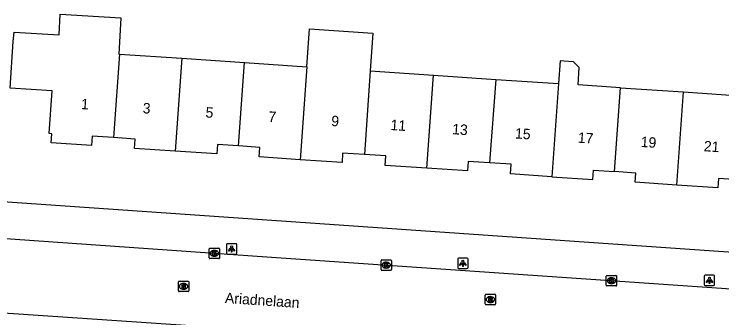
# Model space of a CAD drawing. Extents: x 161848 to 162726, y 385382 to 386521.
# Drawn here: x 162018.3 to 162086.1, y 385519.3 to 385548.4 of the extents above; entities that cross this region are included whole.
import ezdxf

# ---------------------------------------------------------------- set-up
doc = ezdxf.new("R2010")
doc.units = 0
for name, color, linetype in [('IMGEO_Kolk', 7, 'Continuous'), ('IMGEO_Lichtpunt', 7, 'Continuous'), ('IMGEO_Openbare_ruimte_label', 7, 'Continuous'), ('IMGEO_Pand', 7, 'Continuous'), ('IMGEO_Pand_nummerreeks', 7, 'Continuous'), ('IMGEO_Rijbaan_lokaal_open', 7, 'Continuous'), ('IMGEO_Rioolput', 7, 'Continuous'), ('IMGEO_Voetpad_open', 7, 'Continuous')]:
    doc.layers.add(name, color=color, linetype=linetype)

msp = doc.modelspace()

# ---------------------------------------------------------------- linework, layer by layer
at = {"layer": 'IMGEO_Kolk'}
for p, q in [((162037.014, 385525.047), (162037.014, 385525.899)), ((162037.089, 385525.973), (162037.941, 385525.973)), ((162037.502, 385525.753), (162037.527, 385525.753)), ((162038.015, 385525.899), (162038.015, 385525.047)), ((162037.941, 385524.973), (162037.089, 385524.973)), ((162037.525, 385525.193), (162037.5, 385525.193)), ((162053.474, 385523.918), (162053.474, 385524.77)), ((162053.549, 385524.844), (162054.401, 385524.844)), ((162054.475, 385524.77), (162054.475, 385523.918)), ((162053.985, 385524.064), (162053.96, 385524.064)), ((162053.962, 385524.624), (162053.987, 385524.624)), ((162054.401, 385523.844), (162053.549, 385523.844)), ((162075.03, 385522.434), (162075.03, 385523.286)), ((162075.105, 385523.36), (162075.957, 385523.36)), ((162076.031, 385523.286), (162076.031, 385522.434)), ((162075.518, 385523.14), (162075.543, 385523.14)), ((162075.957, 385522.36), (162075.105, 385522.36)), ((162075.541, 385522.58), (162075.516, 385522.58))]:
    msp.add_line(p, q, dxfattribs=at)
for points in [[(162037.014, 385525.047), (162037.014, 385525.899)], [(162037.089, 385525.973), (162037.941, 385525.973)], [(162037.335, 385525.673), (162037.458, 385525.673), (162037.458, 385525.522), (162037.588, 385525.673), (162037.752, 385525.673), (162037.606, 385525.522), (162037.759, 385525.273), (162037.607, 385525.273), (162037.522, 385525.437), (162037.458, 385525.37), (162037.458, 385525.273), (162037.335, 385525.273), (162037.335, 385525.673)], [(162038.015, 385525.899), (162038.015, 385525.047)], [(162037.941, 385524.973), (162037.089, 385524.973)], [(162053.474, 385523.918), (162053.474, 385524.77)], [(162053.549, 385524.844), (162054.401, 385524.844)], [(162054.475, 385524.77), (162054.475, 385523.918)], [(162053.795, 385524.544), (162053.918, 385524.544), (162053.918, 385524.393), (162054.048, 385524.544), (162054.212, 385524.544), (162054.066, 385524.393), (162054.219, 385524.144), (162054.067, 385524.144), (162053.982, 385524.308), (162053.918, 385524.241), (162053.918, 385524.144), (162053.795, 385524.144), (162053.795, 385524.544)], [(162054.401, 385523.844), (162053.549, 385523.844)], [(162075.03, 385522.434), (162075.03, 385523.286)], [(162075.105, 385523.36), (162075.957, 385523.36)], [(162076.031, 385523.286), (162076.031, 385522.434)], [(162075.351, 385523.06), (162075.474, 385523.06), (162075.474, 385522.909), (162075.604, 385523.06), (162075.768, 385523.06), (162075.622, 385522.909), (162075.775, 385522.66), (162075.623, 385522.66), (162075.538, 385522.824), (162075.474, 385522.757), (162075.474, 385522.66), (162075.351, 385522.66), (162075.351, 385523.06)], [(162075.957, 385522.36), (162075.105, 385522.36)]]:
    msp.add_lwpolyline(points, dxfattribs=at)
for centre, start, end in [((162037.091, 385525.897), 91.55205, 178.44795), ((162037.091, 385525.897), 91.55205, 178.44795), ((162037.939, 385525.897), 1.55205, 88.44795), ((162037.939, 385525.897), 1.55205, 88.44795), ((162037.091, 385525.049), 181.55205, 268.44795), ((162037.091, 385525.049), 181.55205, 268.44795), ((162037.939, 385525.049), 271.55205, 358.44795), ((162037.939, 385525.049), 271.55205, 358.44795), ((162053.551, 385524.768), 91.55205, 178.44795), ((162053.551, 385524.768), 91.55205, 178.44795), ((162054.399, 385524.768), 1.55205, 88.44795), ((162054.399, 385524.768), 1.55205, 88.44795), ((162053.551, 385523.92), 181.55205, 268.44795), ((162053.551, 385523.92), 181.55205, 268.44795), ((162054.399, 385523.92), 271.55205, 358.44795), ((162054.399, 385523.92), 271.55205, 358.44795), ((162075.107, 385523.284), 91.55205, 178.44795), ((162075.107, 385523.284), 91.55205, 178.44795), ((162075.955, 385523.284), 1.55205, 88.44795), ((162075.955, 385523.284), 1.55205, 88.44795), ((162075.107, 385522.436), 181.55205, 268.44795), ((162075.107, 385522.436), 181.55205, 268.44795), ((162075.955, 385522.436), 271.55205, 358.44795), ((162075.955, 385522.436), 271.55205, 358.44795)]:
    msp.add_arc(centre, 0.0765, start, end, dxfattribs=at)
for centre, major_axis, ratio, start_param, end_param in [((162037.501, 385525.473), (-0.387, 0.002), 0.722429, 4.712389, 7.853982), ((162037.526, 385525.473), (-0.39, 0.002), 0.717154, 1.570796, 4.712389), ((162053.961, 385524.344), (-0.387, 0.002), 0.722429, 4.712389, 7.853982), ((162053.986, 385524.344), (-0.39, 0.002), 0.717154, 1.570796, 4.712389), ((162075.517, 385522.86), (-0.387, 0.002), 0.722429, 4.712389, 7.853982), ((162075.542, 385522.86), (-0.39, 0.002), 0.717154, 1.570796, 4.712389)]:
    msp.add_ellipse(centre, major_axis=major_axis, ratio=ratio, start_param=start_param, end_param=end_param, dxfattribs=at)
at = {"layer": 'IMGEO_Lichtpunt'}
for p, q in [((162038.67, 385526.304), (162038.67, 385525.497)), ((162038.67, 385526.304), (162038.67, 385525.497)), ((162039.572, 385526.399), (162038.764, 385526.399)), ((162039.572, 385526.399), (162038.764, 385526.399)), ((162039.666, 385525.497), (162039.666, 385526.304)), ((162039.666, 385525.497), (162039.666, 385526.304)), ((162038.764, 385525.403), (162039.572, 385525.403)), ((162038.764, 385525.403), (162039.572, 385525.403)), ((162060.812, 385524.927), (162060.812, 385524.12)), ((162060.812, 385524.927), (162060.812, 385524.12)), ((162061.714, 385525.022), (162060.906, 385525.022)), ((162061.714, 385525.022), (162060.906, 385525.022)), ((162061.808, 385524.12), (162061.808, 385524.927)), ((162061.808, 385524.12), (162061.808, 385524.927)), ((162060.906, 385524.026), (162061.714, 385524.026)), ((162060.906, 385524.026), (162061.714, 385524.026)), ((162084.413, 385523.297), (162084.413, 385522.49)), ((162084.413, 385523.297), (162084.413, 385522.49)), ((162085.315, 385523.392), (162084.507, 385523.392)), ((162085.315, 385523.392), (162084.507, 385523.392)), ((162085.409, 385522.49), (162085.409, 385523.297)), ((162085.409, 385522.49), (162085.409, 385523.297)), ((162084.507, 385522.396), (162085.315, 385522.396)), ((162084.507, 385522.396), (162085.315, 385522.396))]:
    msp.add_line(p, q, dxfattribs=at)
for points in [[(162039.044, 385525.968), (162039.083, 385525.94), (162038.895, 385525.678), (162038.857, 385525.705), (162039.044, 385525.968)], [(162039.146, 385525.92), (162039.193, 385525.92), (162039.193, 385525.598), (162039.146, 385525.598), (162039.146, 385525.92)], [(162039.256, 385525.94), (162039.294, 385525.967), (162039.481, 385525.705), (162039.442, 385525.677), (162039.256, 385525.94)], [(162061.186, 385524.591), (162061.225, 385524.563), (162061.037, 385524.301), (162060.999, 385524.328), (162061.186, 385524.591)], [(162061.288, 385524.543), (162061.335, 385524.543), (162061.335, 385524.221), (162061.288, 385524.221), (162061.288, 385524.543)], [(162061.398, 385524.563), (162061.436, 385524.59), (162061.623, 385524.328), (162061.584, 385524.3), (162061.398, 385524.563)], [(162084.787, 385522.961), (162084.826, 385522.933), (162084.638, 385522.671), (162084.6, 385522.698), (162084.787, 385522.961)], [(162084.889, 385522.913), (162084.936, 385522.913), (162084.936, 385522.591), (162084.889, 385522.591), (162084.889, 385522.913)], [(162084.999, 385522.933), (162085.037, 385522.96), (162085.224, 385522.698), (162085.185, 385522.67), (162084.999, 385522.933)]]:
    msp.add_lwpolyline(points, dxfattribs=at)
for centre in [(162039.169, 385526.102), (162061.311, 385524.725), (162084.912, 385523.095)]:
    msp.add_circle(centre, 0.0994, dxfattribs=at)
for centre, start, end in [((162038.764, 385526.304), 90, 180), ((162038.764, 385526.304), 90, 180), ((162039.572, 385526.304), 0, 90), ((162039.572, 385526.304), 0, 90), ((162038.764, 385525.497), 180, 270), ((162038.764, 385525.497), 180, 270), ((162039.572, 385525.497), 270, 0), ((162039.572, 385525.497), 270, 360), ((162060.906, 385524.927), 90, 180), ((162060.906, 385524.927), 90, 180), ((162061.714, 385524.927), 0, 90), ((162061.714, 385524.927), 0, 90), ((162060.906, 385524.12), 180, 270), ((162060.906, 385524.12), 180, 270), ((162061.714, 385524.12), 270, 0), ((162061.714, 385524.12), 270, 360), ((162084.507, 385523.297), 90, 180), ((162084.507, 385523.297), 90, 180), ((162085.315, 385523.297), 0, 90), ((162085.315, 385523.297), 0, 90), ((162084.507, 385522.49), 180, 270), ((162084.507, 385522.49), 180, 270), ((162085.315, 385522.49), 270, 0), ((162085.315, 385522.49), 270, 360)]:
    msp.add_arc(centre, 0.0946, start, end, dxfattribs=at)
at = {"layer": 'IMGEO_Pand'}
for points in [[(162027.865, 385536.544), (162025.809, 385536.682), (162025.75, 385535.797), (162021.899, 385536.054), (162021.957, 385536.917), (162021.708, 385536.934), (162021.982, 385541.025), (162017.971, 385541.293), (162018.268, 385545.743), (162018.352, 385546.644), (162022.673, 385546.367), (162022.763, 385548.358), (162028.557, 385547.998), (162028.367, 385544.537), (162028.431, 385544.533)], [(162046.373, 385543.331), (162046.638, 385546.964), (162052.692, 385546.546), (162052.437, 385542.925)], [(162028.431, 385544.533), (162027.865, 385536.544)], [(162028.431, 385544.533), (162034.4, 385544.133)], [(162034.4, 385544.133), (162033.771, 385535.247)], [(162034.4, 385544.133), (162040.398, 385543.731)], [(162039.839, 385535.745), (162040.398, 385543.731)], [(162040.398, 385543.731), (162046.373, 385543.331)], [(162076.413, 385541.319), (162072.333, 385541.592), (162072.453, 385543.249), (162071.911, 385543.785), (162070.981, 385543.852), (162070.631, 385543.878), (162070.474, 385541.717)], [(162046.373, 385543.331), (162045.724, 385534.431)], [(162052.437, 385542.925), (162051.875, 385534.932)], [(162052.437, 385542.925), (162058.492, 385542.519)], [(162057.871, 385533.612), (162058.492, 385542.519)], [(162058.492, 385542.519), (162064.463, 385542.12)], [(162064.463, 385542.12), (162063.864, 385534.135)], [(162064.463, 385542.12), (162070.474, 385541.717)], [(162070.474, 385541.717), (162069.827, 385532.804)], [(162075.813, 385533.294), (162076.413, 385541.319)], [(162076.413, 385541.319), (162082.426, 385540.917)], [(162082.426, 385540.917), (162088.735, 385540.494), (162088.297, 385533.941), (162088.198, 385532.464), (162085.788, 385532.626), (162085.729, 385531.74), (162081.793, 385532.003)], [(162081.793, 385532.003), (162082.426, 385540.917)], [(162033.771, 385535.247), (162029.858, 385535.509), (162029.919, 385536.407), (162027.865, 385536.544)], [(162039.839, 385535.745), (162037.823, 385535.88), (162037.763, 385534.98), (162033.771, 385535.247)], [(162045.724, 385534.431), (162041.813, 385534.693), (162041.874, 385535.609), (162039.839, 385535.745)], [(162051.875, 385534.932), (162049.799, 385535.071), (162049.738, 385534.162), (162045.724, 385534.431)], [(162057.871, 385533.612), (162053.861, 385533.881), (162053.922, 385534.795), (162051.875, 385534.932)], [(162063.864, 385534.135), (162061.803, 385534.273), (162061.741, 385533.353), (162057.871, 385533.612)], [(162069.827, 385532.804), (162065.854, 385533.07), (162065.916, 385533.998), (162063.864, 385534.135)], [(162069.827, 385532.804), (162073.761, 385532.541), (162073.82, 385533.427), (162075.813, 385533.294)], [(162081.793, 385532.003), (162077.809, 385532.27), (162077.868, 385533.156), (162075.813, 385533.294)]]:
    msp.add_lwpolyline(points, dxfattribs=at)
at = {"layer": 'IMGEO_Rijbaan_lokaal_open'}
for points in [[(162015.014, 385527.081), (162018.004, 385526.862), (162042.972, 385525.1), (162086.98, 385522.071)], [(162054.531, 385517.227), (162018.299, 385519.675), (162014.628, 385519.918)]]:
    msp.add_lwpolyline(points, dxfattribs=at)
at = {"layer": 'IMGEO_Rioolput'}
for p, q in [((162034.073, 385521.886), (162034.073, 385522.738)), ((162034.148, 385522.812), (162035, 385522.812)), ((162035.074, 385522.738), (162035.074, 385521.886)), ((162034.584, 385522.032), (162034.559, 385522.032)), ((162034.561, 385522.592), (162034.586, 385522.592)), ((162035, 385521.812), (162034.148, 385521.812)), ((162063.438, 385520.63), (162063.438, 385521.482)), ((162063.513, 385521.556), (162064.365, 385521.556)), ((162063.926, 385521.336), (162063.951, 385521.336)), ((162064.439, 385521.482), (162064.439, 385520.63)), ((162063.949, 385520.776), (162063.924, 385520.776)), ((162064.365, 385520.556), (162063.513, 385520.556))]:
    msp.add_line(p, q, dxfattribs=at)
for points in [[(162034.073, 385521.886), (162034.073, 385522.738)], [(162034.148, 385522.812), (162035, 385522.812)], [(162035.074, 385522.738), (162035.074, 385521.886)], [(162034.662, 385522.51), (162034.41, 385522.512), (162034.41, 385522.112)], [(162034.41, 385522.112), (162034.534, 385522.112), (162034.534, 385522.274), (162034.545, 385522.274)], [(162034.588, 385522.431), (162034.534, 385522.431), (162034.534, 385522.35)], [(162034.534, 385522.35), (162034.586, 385522.35)], [(162034.592, 385522.245), (162034.663, 385522.112), (162034.803, 385522.112), (162034.738, 385522.238)], [(162035, 385521.812), (162034.148, 385521.812)], [(162063.438, 385520.63), (162063.438, 385521.482)], [(162063.513, 385521.556), (162064.365, 385521.556)], [(162064.027, 385521.254), (162063.775, 385521.256), (162063.775, 385520.856)], [(162064.439, 385521.482), (162064.439, 385520.63)], [(162063.775, 385520.856), (162063.899, 385520.856), (162063.899, 385521.018), (162063.91, 385521.018)], [(162063.953, 385521.175), (162063.899, 385521.175), (162063.899, 385521.094)], [(162063.899, 385521.094), (162063.951, 385521.094)], [(162063.957, 385520.989), (162064.028, 385520.856), (162064.168, 385520.856), (162064.103, 385520.982)], [(162064.365, 385520.556), (162063.513, 385520.556)]]:
    msp.add_lwpolyline(points, dxfattribs=at)
for centre, radius, start, end in [((162034.15, 385522.736), 0.0765, 91.55205, 178.44795), ((162034.15, 385522.736), 0.0765, 91.55205, 178.44795), ((162034.998, 385522.736), 0.0765, 1.55205, 88.44795), ((162034.998, 385522.736), 0.0765, 1.55205, 88.44795), ((162034.544, 385522.221), 0.0533, 26.02933, 88.69889), ((162034.57, 385522.539), 0.19, 274.7715, 282.96867), ((162034.594, 385522.335), 0.0964, 77.00612, 93.18647), ((162034.608, 385522.392), 0.0378, 276.66336, 79.67722), ((162034.661, 385522.4), 0.109, 350.36119, 89.41601), ((162034.659, 385522.4), 0.112, 277.58423, 350.98172), ((162034.643, 385522.185), 0.108, 29.51342, 73.79051), ((162034.15, 385521.888), 0.0765, 181.55205, 268.44795), ((162034.15, 385521.888), 0.0765, 181.55205, 268.44795), ((162034.998, 385521.888), 0.0765, 271.55205, 358.44795), ((162034.998, 385521.888), 0.0765, 271.55205, 358.44795), ((162063.515, 385521.48), 0.0765, 91.55205, 178.44795), ((162063.515, 385521.48), 0.0765, 91.55205, 178.44795), ((162064.026, 385521.144), 0.109, 350.36119, 89.41601), ((162064.363, 385521.48), 0.0765, 1.55205, 88.44795), ((162064.363, 385521.48), 0.0765, 1.55205, 88.44795), ((162063.515, 385520.632), 0.0765, 181.55205, 268.44795), ((162063.515, 385520.632), 0.0765, 181.55205, 268.44795), ((162063.909, 385520.965), 0.0533, 26.02933, 88.69889), ((162063.935, 385521.283), 0.19, 274.7715, 282.96867), ((162063.959, 385521.079), 0.0964, 77.00612, 93.18647), ((162063.973, 385521.136), 0.0378, 276.66336, 79.67722), ((162064.024, 385521.144), 0.112, 277.58423, 350.98172), ((162064.008, 385520.929), 0.108, 29.51342, 73.79051), ((162064.363, 385520.632), 0.0765, 271.55205, 358.44795), ((162064.363, 385520.632), 0.0765, 271.55205, 358.44795)]:
    msp.add_arc(centre, radius, start, end, dxfattribs=at)
for centre, major_axis, ratio, start_param, end_param in [((162034.56, 385522.312), (-0.387, 0.002), 0.722429, 4.712389, 7.853982), ((162034.585, 385522.312), (-0.39, 0.002), 0.717154, 1.570796, 4.712389), ((162063.925, 385521.056), (-0.387, 0.002), 0.722429, 4.712389, 7.853982), ((162063.95, 385521.056), (-0.39, 0.002), 0.717154, 1.570796, 4.712389)]:
    msp.add_ellipse(centre, major_axis=major_axis, ratio=ratio, start_param=start_param, end_param=end_param, dxfattribs=at)
at = {"layer": 'IMGEO_Voetpad_open'}
msp.add_lwpolyline([(162089.014, 385525.433), (162087.624, 385525.529), (162018.636, 385530.301), (162016.402, 385530.453)], dxfattribs=at)

# ---------------------------------------------------------------- texts
at = {"layer": 'IMGEO_Openbare_ruimte_label'}
msp.add_text('Ariadnelaan', height=1, rotation=356.1021, dxfattribs=at).set_placement((162038.511, 385520.729))
at = {"layer": 'IMGEO_Pand_nummerreeks'}
for s, rotation, p in [('1', 356.13253, (162024.727, 385539.281)), ('3', 356.13134, (162030.63, 385538.882)), ('5', 356.13134, (162036.647, 385538.475)), ('7', 356.13134, (162042.664, 385538.068)), ('9', 356.13253, (162048.682, 385537.662)), ('11', 356.13134, (162054.355, 385537.278)), ('13', 356.13134, (162060.258, 385536.878)), ('15', 356.13134, (162066.275, 385536.471)), ('17', 356.13253, (162072.292, 385536.064)), ('19', 356.13134, (162078.309, 385535.657)), ('21', 356.13253, (162084.349, 385535.249))]:
    msp.add_text(s, height=1, rotation=rotation, dxfattribs=at).set_placement(p)

doc.saveas('drawing.dxf')
